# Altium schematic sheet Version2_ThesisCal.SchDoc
size A2; SheetNumber: 1; SheetTotal: 1; SPICEModelCacheJMJTSHEM: <root> / <DocumentId>JMJTSHEM</DocumentId> / </root>
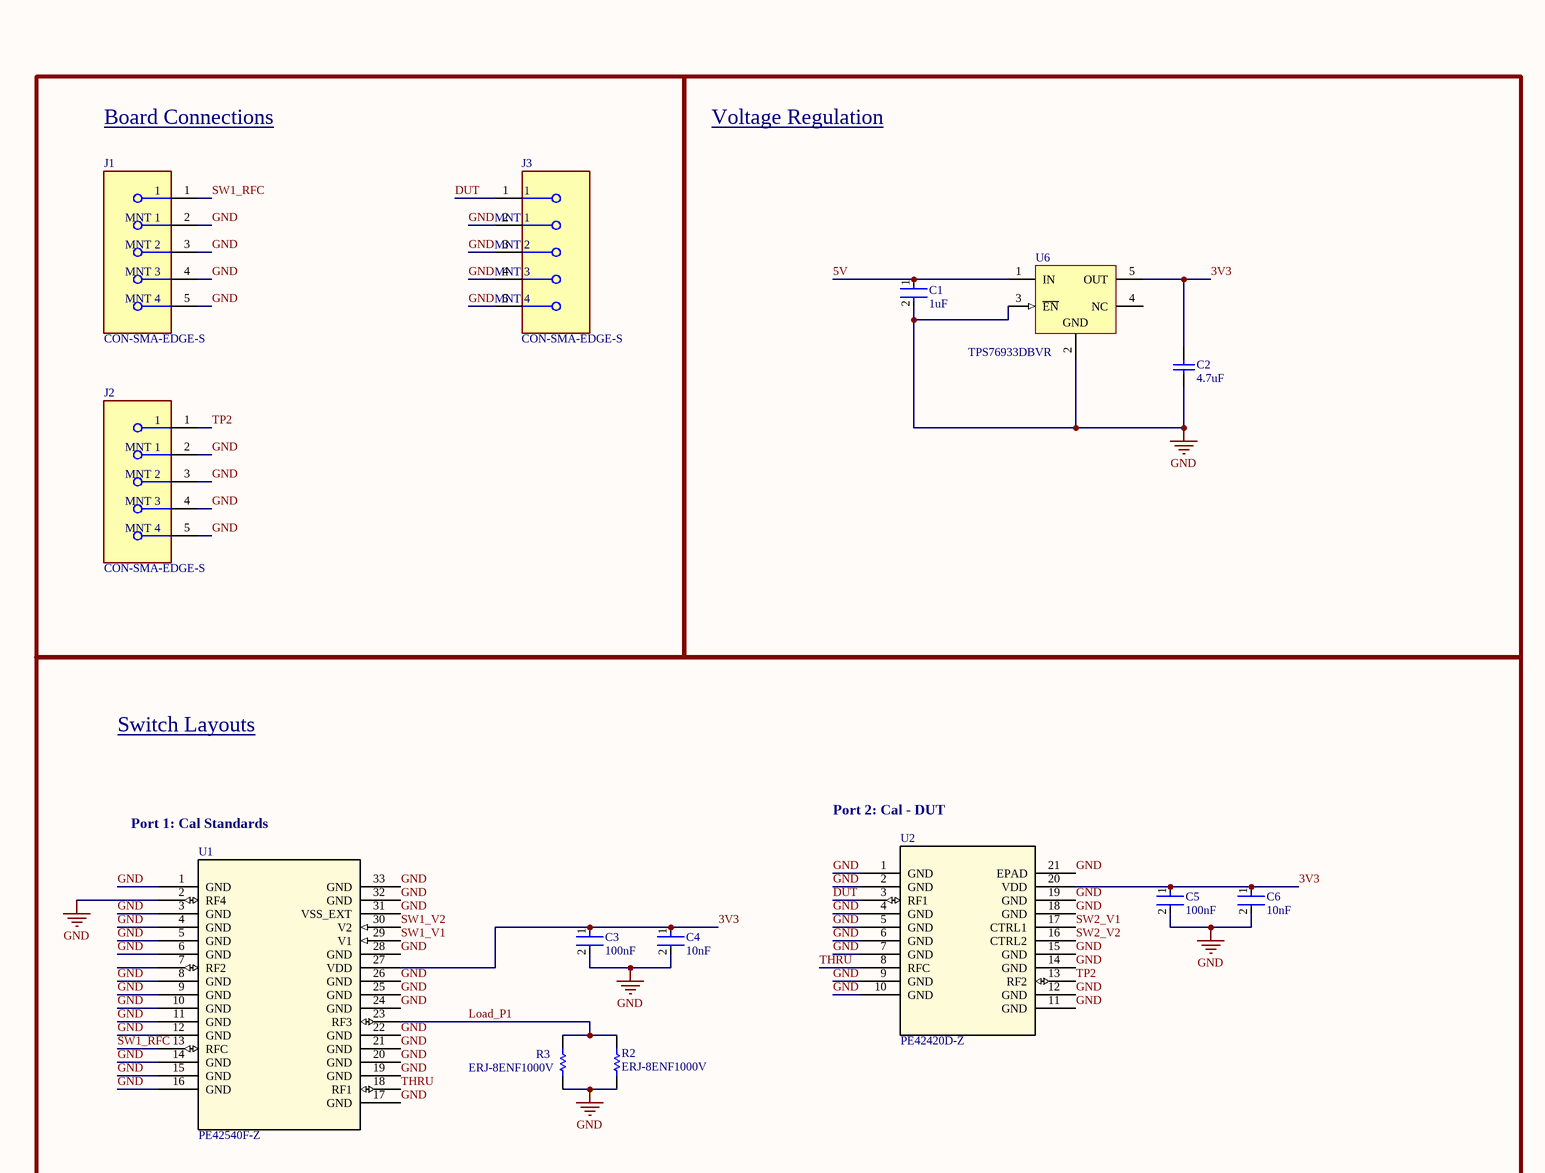
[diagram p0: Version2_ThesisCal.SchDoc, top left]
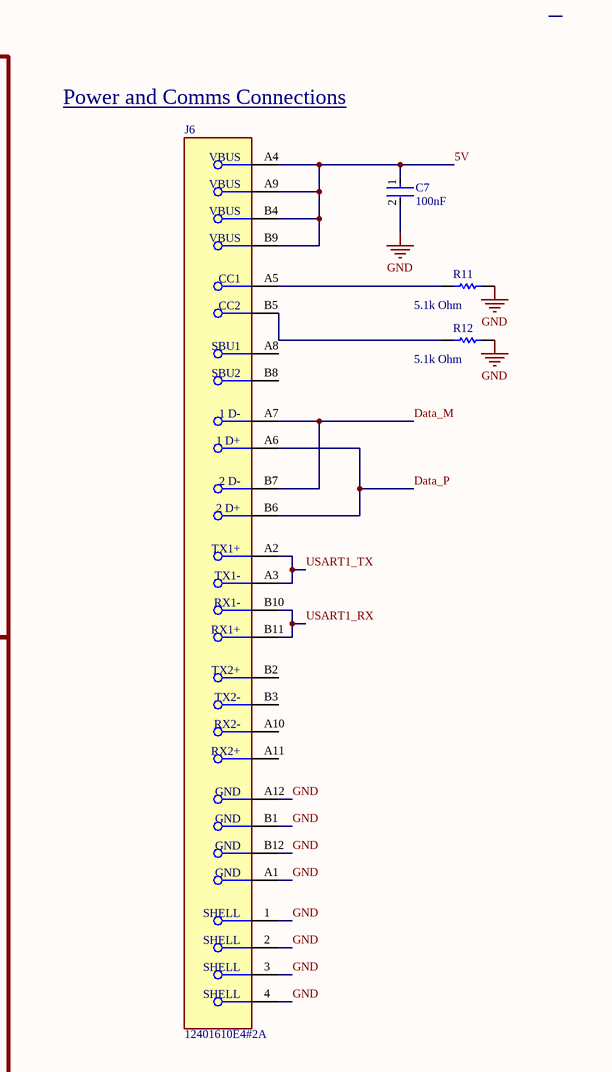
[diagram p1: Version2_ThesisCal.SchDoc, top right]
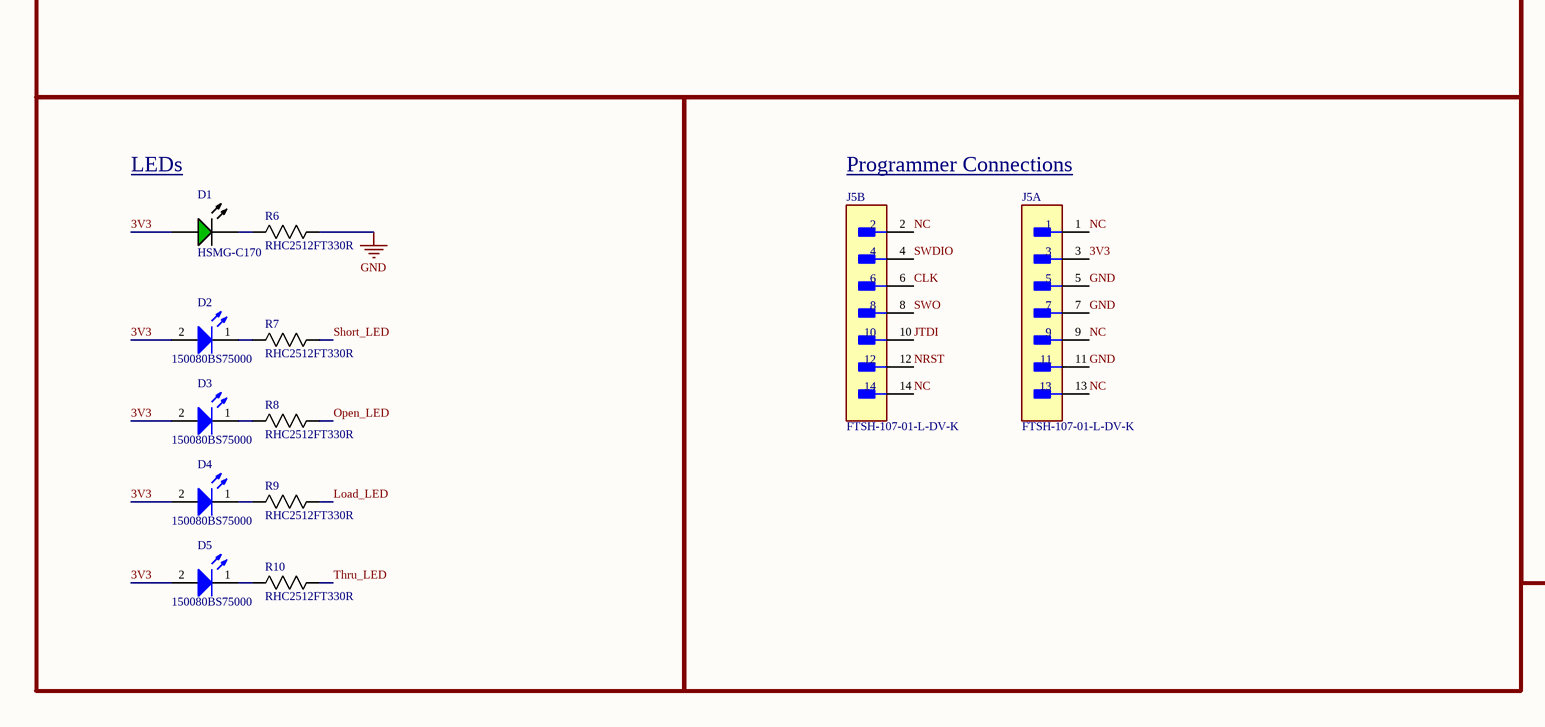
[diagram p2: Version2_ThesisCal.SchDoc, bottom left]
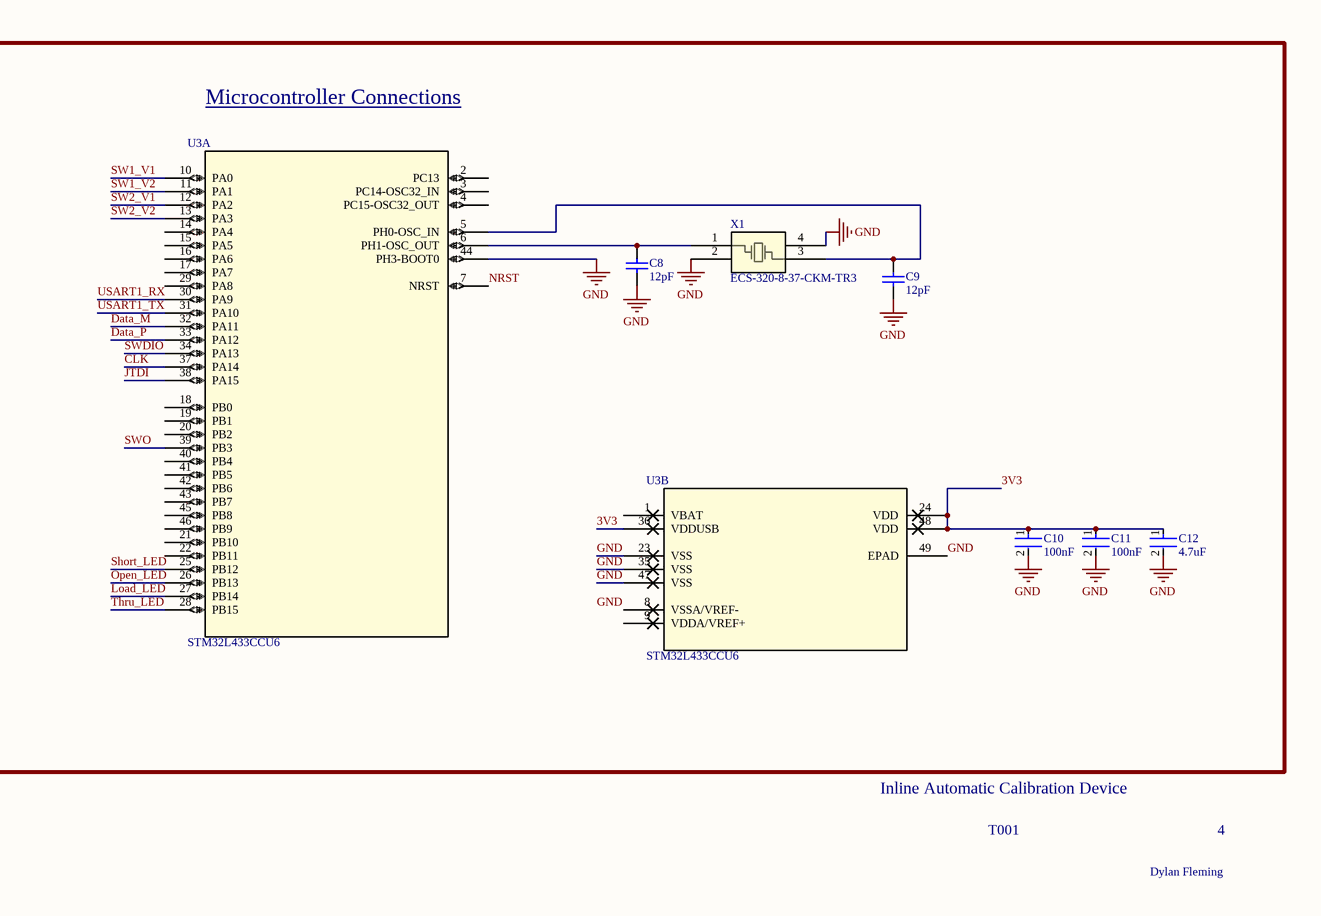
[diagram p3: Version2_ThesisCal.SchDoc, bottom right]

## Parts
C1  1uF  [FP-C1608-080-0_1-IPC_B]
C2  4.7uF  [CAPC2013X135X45LL10T25]
C3  100nF  [FP-1206-L_3_2_0_2-W_1_6_0-MFG]
C4  10nF  [FP-C0805C-DN-MFG]
C5  100nF  [FP-1206-L_3_2_0_2-W_1_6_0-MFG]
C6  10nF  [FP-C0805C-DN-MFG]
C7  100nF  [FP-1206-L_3_2_0_2-W_1_6_0-MFG]
C8  12pF  [CAPC2013X115X51NL20T26]
C9  12pF  [CAPC2013X115X51NL20T26]
C10  100nF  [FP-1206-L_3_2_0_2-W_1_6_0-MFG]
C11  100nF  [FP-1206-L_3_2_0_2-W_1_6_0-MFG]
C12  4.7uF  [FP-C2012-125-0_2-IPC_C]
D1  HSMG-C170  [AVAG-HSMX-C170_V]
D2  150080BS75000  [WL-SMCW_0805_150080xx75000]
D3  150080BS75000  [WL-SMCW_0805_150080xx75000]
D4  150080BS75000  [WL-SMCW_0805_150080xx75000]
D5  150080BS75000  [WL-SMCW_0805_150080xx75000]
J1  CON-SMA-EDGE-S  [FP-CON-SMA-EDGE-S-MFG]
J2  CON-SMA-EDGE-S  [FP-CON-SMA-EDGE-S-MFG]
J3  CON-SMA-EDGE-S  [FP-CON-SMA-EDGE-S-MFG]
J5  FTSH-107-01-L-DV-K  [FP-FTSH-107-01-L-DV-K-MFG]  (parts A,B of 2)
J6  12401610E4#2A  [FP-12401610E4#2A-MFG]
R2  ERJ-8ENF1000V  [RESC3216X70X50NL05T20]
R3  ERJ-8ENF1000V  [RESC3216X70X50NL05T20]
R6  RHC2512FT330R  [STA_RHC2512_STP]
R7  RHC2512FT330R  [STA_RHC2512_STP]
R8  RHC2512FT330R  [STA_RHC2512_STP]
R9  RHC2512FT330R  [STA_RHC2512_STP]
R10  RHC2512FT330R  [STA_RHC2512_STP]
R11  5.1k Ohm  [RESC3216X50X50NL20T25]
R12  5.1k Ohm  [RESC3216X50X50NL20T25]
U1  PE42540F-Z  [PE42540G-Z]
U2  PE42420D-Z  [LGA20_4X4_PSM]
U3  STM32L433CCU6  [UFQFPN48-7x7mm]  (parts A,B of 2)
U6  TPS76933DBVR  [DBV0005A_L]
X1  ECS-320-8-37-CKM-TR3  [NX2016SA_NDK]

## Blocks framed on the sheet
Board Connections: J1-J3
Voltage Regulation: C1 C2 U6
Switch Layouts: C3-C6 R2 R3 U1 U2
Microcontroller Connections: C8-C12 U3 X1
LEDs: D1-D5 R6-R10
Programmer Connections: J5

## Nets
GND: C1.2 C2.1 C3.2 C4.2 C5.2 C6.2 C7.2 C8.1 C9.1 C10.2 C11.2 C12.2 J1.2(MNT_1) J1.3(MNT_2) J1.4(MNT_3) J1.5(MNT_4) J2.2(MNT_1) J2.3(MNT_2) J2.4(MNT_3) J2.5(MNT_4) J3.2(MNT_1) J3.3(MNT_2) J3.4(MNT_3) J3.5(MNT_4) J5.5 J5.7 J5.11 J6.1(SHELL) J6.2(SHELL) J6.3(SHELL) J6.4(SHELL) J6.A1(GND) J6.A12(GND) J6.B1(GND) J6.B12(GND) R2.2 R3.2 R6.2 R11.2 R12.2 U1.1(GND) U1.2(RF4) U1.3(GND) U1.4(GND) U1.5(GND) U1.6(GND) U1.8(GND) U1.9(GND) U1.10(GND) U1.11(GND) U1.12(GND) U1.14(GND) U1.15(GND) U1.16(GND) U1.17(GND) U1.19(GND) U1.20(GND) U1.21(GND) U1.22(GND) U1.24(GND) U1.25(GND) U1.26(GND) U1.28(GND) U1.31(VSS_EXT) U1.32(GND) U1.33(GND) U2.1(GND) U2.2(GND) U2.4(GND) U2.5(GND) U2.6(GND) U2.7(GND) U2.9(GND) U2.10(GND) U2.11(GND) U2.12(GND) U2.14(GND) U2.15(GND) U2.18(GND) U2.19(GND) U2.21(EPAD) U3.23(VSS) U3.35(VSS) U3.44(PH3-BOOT0) U3.47(VSS) U3.49(EPAD) U6.2(GND) U6.3(~{EN}) X1.2 X1.4
3V3: C2.2 C3.1 C4.1 C5.1 C6.1 C10.1 C11.1 C12.1 D1.1(A) D2.2(A) D3.2(A) D4.2(A) D5.2(A) J5.3 U1.27(VDD) U2.20(VDD) U3.24(VDD) U3.36(VDDUSB) U3.48(VDD) U6.5(OUT)
5V: C1.1 C7.1 J6.A4(VBUS) J6.A9(VBUS) J6.B4(VBUS) J6.B9(VBUS) U6.1(IN)
CLK: J5.6 U3.37(PA14)
Data_M: J6.A7(1_D-) J6.B7(2_D-) U3.32(PA11)
Data_P: J6.A6(1_D+) J6.B6(2_D+) U3.33(PA12)
DUT: J3.1 U2.3(RF1)
JTDI: J5.10 U3.38(PA15)
Load_LED: R9.2 U3.27(PB14)
Load_P1: R2.1 R3.1 U1.23(RF3)
NC: J5.1 J5.2 J5.9 J5.13 J5.14
NRST: J5.12 U3.7(NRST)
Open_LED: R8.2 U3.26(PB13)
Short_LED: R7.2 U3.25(PB12)
SW1_RFC: J1.1 U1.13(RFC)
SW1_V1: U1.29(V1) U3.10(PA0)
SW1_V2: U1.30(V2) U3.11(PA1)
SW2_V1: U2.17(CTRL1) U3.12(PA2)
SW2_V2: U2.16(CTRL2) U3.13(PA3)
SWDIO: J5.4 U3.34(PA13)
SWO: J5.8 U3.39(PB3)
THRU: U1.18(RF1) U2.8(RFC)
Thru_LED: R10.2 U3.28(PB15)
TP2: J2.1 U2.13(RF2)
USART1_RX: J6.B10(RX1-) J6.B11(RX1+) U3.30(PA9)
USART1_TX: J6.A2(TX1+) J6.A3(TX1-) U3.31(PA10)
NetC8_2: C8.2 U3.6(PH1-OSC_OUT) X1.1
NetC9_2: C9.2 U3.5(PH0-OSC_IN) X1.3
NetD1_2: D1.2(K) R6.1
NetD2_1: D2.1(K) R7.1
NetD3_1: D3.1(K) R8.1
NetD4_1: D4.1(K) R9.1
NetD5_1: D5.1(K) R10.1
NetJ6_A5: J6.A5(CC1) R11.1
NetJ6_B5: J6.B5(CC2) R12.1

Not connected (* = marked no-connect by the designer): J6 A8(SBU1) A10(RX2-) A11(RX2+) B2(TX2+) B3(TX2-) B8(SBU2); U1 7(RF2); U3 1(VBAT) 2(PC13) 3(PC14-OSC32_IN) 4(PC15-OSC32_OUT) 8(VSSA/VREF-) 9(VDDA/VREF+) 14(PA4) 15(PA5) 16(PA6) 17(PA7) 18(PB0) 19(PB1) 20(PB2) 21(PB10) 22(PB11) 29(PA8) 40(PB4) 41(PB5) 42(PB6) 43(PB7) 45(PB8) 46(PB9); U6 4(NC)

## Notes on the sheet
- Power and Comms Connections
- Port 1: Cal Standards
- Port 2: Cal - DUT
- Inline Automatic Calibration Device
- T001
- Dylan Fleming
- 4
- Labels drawn without touching a wire or pin: GND

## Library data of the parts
C1 = CMP-2000-06025-2: Multilayer Ceramic Capacitors 1μF ±10% 50V X5R SMD 0603
C2 = CMP-1662-00015-2: Chip Capacitor, 4.7 uF, +/- 10%, 16 V, -55 to 85 degC, 0805 (2012 Metric), RoHS, Tape and Reel; PartNumber: GRM21BR61C475KA88L; Voltage Rating (DC): 16 V; Type (Capacitors): X5R; Case\/Package: 0805
C3 C5 C7 C10 C11 = CMP-04427-004798-1: General Purpose Ceramic Capacitor, 1206, 100nF, 10%, X7R, 15%, 100V
C4 C6 = CMP-2007-00259-2: CAP CER 10000PF 200V X7R 0805; Manufacturer Part Number: C0805C103K2RACTU; Manufacturer: KEMET; Material: Ceramic; Temperature Coefficient: 30ppm/°C; Capacitance: 10,000 pF; Tolerance: 0.1; Value: 10,000 pF
C8 C9 = CMP-2007-04862-1: Manufacturer: AVX Interconnect / Elco; Part Number: 08052U120GAT2A
C12 = CMP-08246-000007-2: Multilayer Ceramic Capacitors 4.7μF ±10% 50V X5R SMD 0805
D1 = CMP-2000-05062-1: Chip LED, Green, 2.2 V, -40 to 85 degC, 2-Pin SMD, Pb-Free, Tape and Reel; Manufacturer: Avago; No. of Pins: 2; Peak Wavelength: 570nm; SVHC: NoSVHC(16-Jun-2014); Dominant Wavelength: 572nm; Forward Current If: 20mA; Viewing Angle: 170deg; Lens Shape: Rectangular; PIV Max: 5V; External Width: 1.25mm; LED Type: Standard; External Depth: 0.8mm; Opto Mounting Orientation: Top; Luminous Intensity: 15mcd; Luminous Intensity Min: 4mcd; Forward Voltage VF Max: 2.6V; External Length / Height: 2mm; Bulb Size: 1.25mmx1.4mm; Light Area Height: 1mm; Voltage Vf Typ: 2.2V
D2-D5 = CMP-1426-00008-6: NexarPartId: 29717779; Test Current: 20mA; Lens Style: Clear, Rectangular; Forward Current: 100mA; Power Dissipation: 105mW; Dominant Wavelength: 470nm; Reverse Voltage: 5V; Viewing Angle: 140°; Luminous Intensity: 145mcd; Color: Blue; Forward Voltage: 3.2V; Max Junction Temperature (Tj): 95°C; Peak Wavelength: 465nm
J1-J3 = CMP-204357-000001-1: CONN SMA JACK STR EDGE MNT; Manufacturer: RF Solutions Ltd.; Impedance: 50Ω; Conn Orientation: Right Angle; Is Female: yes; Number Of Contacts: 1; Frequency: 18GHz; Shielding: true
J5 = CMP-02766-001412-1: CONN HEADER SMD 14POS 1.27MM; Number of Contacts: 14; Gender: Male
J6 = CMP-15126-126516878-1: 12401610E4#2A Conn USB Type C RCP 24 POS 0.5mm Solder RA SMD 24 Terminal 1 Port Automotive; Gender: Receptacle; USB Standard: USB 3.1; Number of Contacts: 24; Current Rating: 5A
R2 R3 = CMP-2003-00016-1: Manufacturer: Panasonic
R6-R10 = RHC2512FT330R: No Description Available; Mfr_Name: Stackpole International
R11 R12 = CMP-2003-02609-1: Part Number: RG3216P-5101-B-T5; Manufacturer: Susumu
U1 = PE42540F-Z: No Description Available; Mfr_Name: Peregine Semiconductor
U2 = PE42420D-Z: No Description Available; Mfr_Name: pSemi
U3 = STM32L433CCU6: No Description Available; Mfr_Name: STMicroelectronics
U6 = CMP-0394-00574-2: Single Output LDO, 100 mA, Fixed 3.3 V Output, 2.7 to 10 V Input, with Low IQ, 5-pin SOT-23 (DBV), -40 to 125 degC, Green (RoHS & no Sb/Br); Manufacturer: Texas Instruments; Fixed Output Options(V): 3.3; Iq(Typ)(mA): 0.02; Rating: Catalog; Vin(Max)(V): 10; SubFamily: Single Channel LDO; Iout(Max)(A): 0.1; Vin(Min)(V): 2.7; Accuracy(%): 3; Vdo(Typ)(mV): 98
X1 = NX2016SA-32M-EXS00A-CS06465: No Description Available; Mfr_Name: NDK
